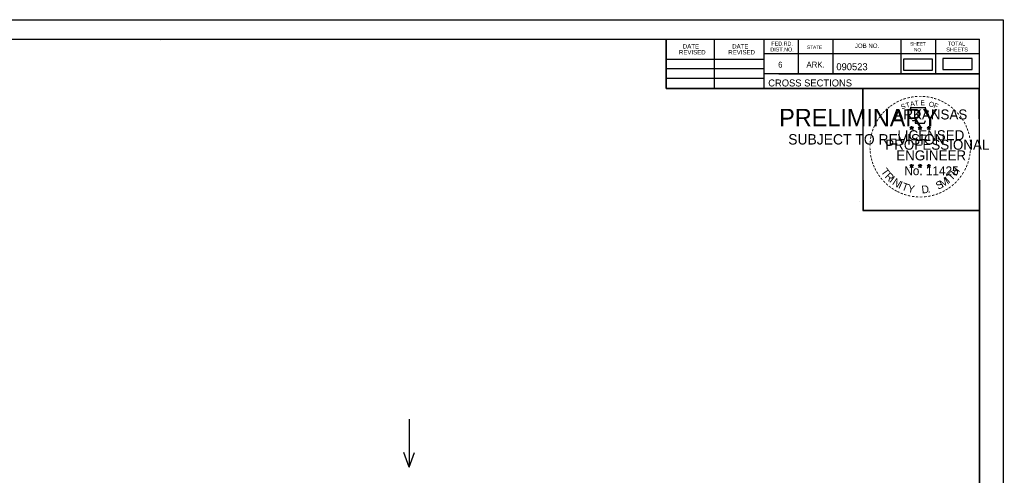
# Model space of a CAD drawing. Extents: x 1406028 to 1412453, y 321733 to 325986.
# Drawn here: x 1406556.2 to 1406752.8, y 323761.7 to 323852.7 of the extents above; entities that cross this region are included whole.
import ezdxf

# ---------------------------------------------------------------- set-up
doc = ezdxf.new("R2010")
doc.units = 0
for name, color, linetype in [('R_Border', 7, 'Continuous'), ('R_Border PE', 7, 'Continuous'), ('R_Border Prem', 7, 'Continuous'), ('R_Fin Surface', 7, 'Continuous'), ('R_No Plot', 7, 'Continuous'), ('R_Water Annot', 7, 'Continuous')]:
    doc.layers.add(name, color=color, linetype=linetype)

msp = doc.modelspace()

# ---------------------------------------------------------------- linework, layer by layer
at = {"layer": 'R_Border'}
for p, q in [((1406431.89, 323848.82), (1406748.07, 323848.82)), ((1406584.41, 323848.56), (1406584.41, 323848.56)), ((1406584.41, 323848.56), (1406584.41, 323848.56)), ((1406685.43, 323838.94), (1406685.43, 323848.82)), ((1406695.11, 323838.94), (1406695.11, 323848.82)), ((1406704.97, 323848.82), (1406704.97, 323838.94)), ((1406711.81, 323848.82), (1406711.81, 323841.88)), ((1406718.75, 323848.82), (1406718.75, 323841.88)), ((1406732.33, 323848.82), (1406732.33, 323841.88)), ((1406739.27, 323848.82), (1406739.27, 323841.88)), ((1406748.07, 323643.36), (1406748.07, 323848.82)), ((1406685.43, 323844.8), (1406704.97, 323844.8)), ((1406748.07, 323845.88), (1406704.97, 323845.88)), ((1406748.07, 323845.9), (1406748.07, 323845.9)), ((1406685.43, 323842.94), (1406704.97, 323842.94)), ((1406685.43, 323841), (1406704.97, 323841)), ((1406748.07, 323841.88), (1406704.97, 323841.88)), ((1406707.93, 323841.88), (1406748.07, 323841.88)), ((1406748.07, 323838.94), (1406685.43, 323838.94))]:
    msp.add_line(p, q, dxfattribs=at)
at = {"layer": 'R_Border PE'}
for p, q in [((1406734.15, 323831.19), (1406734.5, 323831.08)), ((1406734.15, 323831.19), (1406734.41, 323831.15)), ((1406734.15, 323831.19), (1406734.39, 323831.07)), ((1406734.29, 323830.78), (1406734.5, 323831.08)), ((1406734.29, 323830.78), (1406734.41, 323831.03)), ((1406734.29, 323830.78), (1406734.5, 323831)), ((1406734.5, 323831.44), (1406734.46, 323831.19)), ((1406734.5, 323831.08), (1406734.5, 323831.44)), ((1406734.5, 323831.44), (1406734.55, 323831.19)), ((1406734.85, 323831.19), (1406734.5, 323831.08)), ((1406734.72, 323830.78), (1406734.5, 323831.08)), ((1406734.72, 323830.78), (1406734.5, 323831)), ((1406734.85, 323831.19), (1406734.56, 323831.14)), ((1406734.72, 323830.78), (1406734.58, 323831.07)), ((1406734.85, 323831.19), (1406734.65, 323831.09)), ((1406735.82, 323831.19), (1406736.17, 323831.08)), ((1406735.82, 323831.19), (1406736.08, 323831.15)), ((1406735.82, 323831.19), (1406736.06, 323831.07)), ((1406735.96, 323830.78), (1406736.17, 323831.08)), ((1406735.96, 323830.78), (1406736.08, 323831.03)), ((1406735.96, 323830.78), (1406736.17, 323831)), ((1406736.17, 323831.44), (1406736.13, 323831.19)), ((1406736.17, 323831.08), (1406736.17, 323831.44)), ((1406736.17, 323831.44), (1406736.22, 323831.19)), ((1406736.52, 323831.19), (1406736.17, 323831.08)), ((1406736.39, 323830.78), (1406736.17, 323831.08)), ((1406736.39, 323830.78), (1406736.17, 323831)), ((1406736.52, 323831.19), (1406736.23, 323831.14)), ((1406736.39, 323830.78), (1406736.25, 323831.07)), ((1406736.52, 323831.19), (1406736.32, 323831.09)), ((1406737.59, 323831.18), (1406737.94, 323831.07)), ((1406737.59, 323831.18), (1406737.84, 323831.13)), ((1406737.59, 323831.18), (1406737.83, 323831.06)), ((1406737.72, 323830.77), (1406737.94, 323831.07)), ((1406737.72, 323830.77), (1406737.85, 323831.01)), ((1406737.72, 323830.77), (1406737.94, 323830.99)), ((1406737.94, 323831.43), (1406737.9, 323831.18)), ((1406737.94, 323831.07), (1406737.94, 323831.43)), ((1406737.94, 323831.43), (1406737.99, 323831.18)), ((1406738.28, 323831.18), (1406737.94, 323831.07)), ((1406738.15, 323830.77), (1406737.94, 323831.07)), ((1406738.15, 323830.77), (1406737.94, 323830.98)), ((1406738.28, 323831.18), (1406738, 323831.13)), ((1406738.15, 323830.77), (1406738.01, 323831.06)), ((1406738.28, 323831.18), (1406738.08, 323831.08)), ((1406734.15, 323823.62), (1406734.5, 323823.51)), ((1406734.15, 323823.62), (1406734.4, 323823.57)), ((1406734.15, 323823.62), (1406734.39, 323823.5)), ((1406734.28, 323823.21), (1406734.5, 323823.51)), ((1406734.28, 323823.21), (1406734.41, 323823.45)), ((1406734.28, 323823.21), (1406734.5, 323823.43)), ((1406734.5, 323823.87), (1406734.46, 323823.62)), ((1406734.5, 323823.51), (1406734.5, 323823.87)), ((1406734.5, 323823.87), (1406734.55, 323823.62)), ((1406734.85, 323823.62), (1406734.5, 323823.51)), ((1406734.71, 323823.21), (1406734.5, 323823.51)), ((1406734.71, 323823.21), (1406734.5, 323823.42)), ((1406734.85, 323823.62), (1406734.56, 323823.57)), ((1406734.71, 323823.21), (1406734.58, 323823.5)), ((1406734.85, 323823.62), (1406734.64, 323823.52)), ((1406735.82, 323823.62), (1406736.17, 323823.51)), ((1406735.82, 323823.62), (1406736.07, 323823.57)), ((1406735.82, 323823.62), (1406736.06, 323823.5)), ((1406735.95, 323823.21), (1406736.17, 323823.51)), ((1406735.95, 323823.21), (1406736.08, 323823.45)), ((1406735.95, 323823.21), (1406736.17, 323823.43)), ((1406736.17, 323823.87), (1406736.13, 323823.62)), ((1406736.17, 323823.51), (1406736.17, 323823.87)), ((1406736.17, 323823.87), (1406736.22, 323823.62)), ((1406736.52, 323823.62), (1406736.17, 323823.51)), ((1406736.38, 323823.21), (1406736.17, 323823.51)), ((1406736.38, 323823.21), (1406736.17, 323823.42)), ((1406736.52, 323823.62), (1406736.23, 323823.57)), ((1406736.38, 323823.21), (1406736.24, 323823.5)), ((1406736.52, 323823.62), (1406736.31, 323823.52)), ((1406737.59, 323823.61), (1406737.94, 323823.5)), ((1406737.59, 323823.61), (1406737.84, 323823.56)), ((1406737.59, 323823.61), (1406737.82, 323823.49)), ((1406737.72, 323823.2), (1406737.94, 323823.5)), ((1406737.72, 323823.2), (1406737.85, 323823.44)), ((1406737.72, 323823.2), (1406737.93, 323823.42)), ((1406737.94, 323823.86), (1406737.89, 323823.61)), ((1406738.15, 323823.2), (1406737.93, 323823.41)), ((1406737.94, 323823.5), (1406737.94, 323823.86)), ((1406737.94, 323823.86), (1406737.98, 323823.61)), ((1406738.28, 323823.61), (1406737.94, 323823.5)), ((1406738.15, 323823.2), (1406737.94, 323823.5)), ((1406738.28, 323823.61), (1406738, 323823.56)), ((1406738.15, 323823.2), (1406738.01, 323823.49)), ((1406738.28, 323823.61), (1406738.08, 323823.51))]:
    msp.add_line(p, q, dxfattribs=at)
for points in [[(1406734.2, 323835.07), (1406734.46, 323834.24)], [(1406737.71, 323834.15), (1406737.85, 323834.43), (1406737.16, 323834.41), (1406737.31, 323835.07), (1406734.2, 323835.07)], [(1406734.69, 323832.65), (1406734.69, 323832.56), (1406735.25, 323832.54), (1406735.2, 323832.07), (1406737.07, 323832.07), (1406737.27, 323832.6)], [(1406734.5, 323831.44), (1406734.72, 323830.78), (1406734.15, 323831.19), (1406734.85, 323831.19), (1406734.29, 323830.78), (1406734.5, 323831.44)], [(1406736.17, 323831.44), (1406736.39, 323830.78), (1406735.82, 323831.19), (1406736.52, 323831.19), (1406735.96, 323830.78), (1406736.17, 323831.44)], [(1406737.94, 323831.43), (1406738.15, 323830.77), (1406737.59, 323831.18), (1406738.28, 323831.18), (1406737.72, 323830.77), (1406737.94, 323831.43)], [(1406734.5, 323823.87), (1406734.71, 323823.21), (1406734.15, 323823.62), (1406734.85, 323823.62), (1406734.28, 323823.21), (1406734.5, 323823.87)], [(1406736.17, 323823.87), (1406736.38, 323823.21), (1406735.82, 323823.62), (1406736.52, 323823.62), (1406735.95, 323823.21), (1406736.17, 323823.87)], [(1406737.94, 323823.86), (1406738.15, 323823.2), (1406737.59, 323823.61), (1406738.28, 323823.61), (1406737.72, 323823.2), (1406737.94, 323823.86)]]:
    msp.add_lwpolyline(points, dxfattribs=at)
for centre, radius in [((1406734.5, 323831.08), 0.172), ((1406734.5, 323831.08), 0.145), ((1406734.5, 323831.08), 0.116), ((1406734.5, 323831.08), 0.0991), ((1406734.5, 323831.08), 0.0747), ((1406734.5, 323831.08), 0.0495), ((1406734.5, 323831.08), 0.0296), ((1406736.17, 323831.08), 0.172), ((1406736.17, 323831.08), 0.145), ((1406736.17, 323831.08), 0.116), ((1406736.17, 323831.08), 0.0991), ((1406736.17, 323831.08), 0.0747), ((1406736.17, 323831.08), 0.0495), ((1406736.17, 323831.08), 0.0296), ((1406737.94, 323831.07), 0.172), ((1406737.94, 323831.07), 0.145), ((1406737.94, 323831.07), 0.116), ((1406737.94, 323831.07), 0.0991), ((1406737.94, 323831.07), 0.0747), ((1406737.94, 323831.07), 0.0495), ((1406737.94, 323831.07), 0.0296), ((1406734.5, 323823.51), 0.172), ((1406734.5, 323823.51), 0.145), ((1406734.5, 323823.51), 0.116), ((1406734.5, 323823.51), 0.0991), ((1406734.5, 323823.51), 0.0747), ((1406734.5, 323823.51), 0.0495), ((1406734.5, 323823.51), 0.0296), ((1406736.17, 323823.51), 0.172), ((1406736.17, 323823.51), 0.145), ((1406736.17, 323823.51), 0.116), ((1406736.17, 323823.51), 0.0991), ((1406736.17, 323823.51), 0.0747), ((1406736.17, 323823.51), 0.0495), ((1406736.17, 323823.51), 0.0296), ((1406737.93, 323823.5), 0.172), ((1406737.93, 323823.5), 0.145), ((1406737.93, 323823.5), 0.116), ((1406737.93, 323823.5), 0.0991), ((1406737.93, 323823.5), 0.0747), ((1406737.93, 323823.5), 0.0495), ((1406737.93, 323823.5), 0.0296)]:
    msp.add_circle(centre, radius, dxfattribs=at)
at = {"layer": 'R_Fin Surface'}
for points in [[(1406732.85, 323842.65), (1406738.68, 323842.65), (1406738.68, 323844.84), (1406732.85, 323844.84)], [(1406740.76, 323842.76), (1406746.59, 323842.76), (1406746.59, 323844.95), (1406740.76, 323844.95)]]:
    msp.add_lwpolyline(points, close=True, dxfattribs=at)
at = {"layer": 'R_No Plot'}
for p, q in [((1406419.49, 323852.71), (1406752.82, 323852.71)), ((1406724.1, 323816.48), (1406724.1, 323816.48))]:
    msp.add_line(p, q, dxfattribs=at)
for points in [[(1406419.48, 323852.71), (1406752.82, 323852.71), (1406752.82, 323639.37), (1406419.48, 323639.37)], [(1406665.81, 323848.82), (1406685.43, 323848.82), (1406685.43, 323838.94), (1406701.54, 323838.94), (1406724.74, 323838.94), (1406724.74, 323814.6), (1406748.07, 323814.6), (1406748.07, 323643.36), (1406431.89, 323643.36), (1406431.89, 323848.82)], [(1406724.74, 323838.94), (1406747.95, 323838.94), (1406748.07, 323814.6), (1406724.86, 323814.6)]]:
    msp.add_lwpolyline(points, close=True, dxfattribs=at)
at = {"layer": 'R_Water Annot'}
for p, q in [((1406634.04, 323772.88), (1406634.04, 323763.31)), ((1406634.04, 323763.31), (1406632.97, 323766.24)), ((1406634.04, 323763.31), (1406635.1, 323766.24))]:
    msp.add_line(p, q, dxfattribs=at)

# ---------------------------------------------------------------- texts
at = {"layer": 'R_Border'}
for s, height, p in [('FED.RD.', 0.782, (1406706.45, 323847.54)), ('JOB NO.', 0.879, (1406723.15, 323847.06)), ('SHEET', 0.684, (1406734.19, 323847.54)), ('TOTAL', 0.782, (1406741.71, 323847.54)), ('REVISED', 0.879, (1406687.99, 323845.77)), ('DATE', 0.879, (1406688.77, 323846.95)), ('REVISED', 0.879, (1406697.85, 323845.77)), ('DATE', 0.879, (1406698.63, 323846.95)), ('DIST.NO.', 0.782, (1406706.25, 323846.36)), ('STATE', 0.684, (1406713.57, 323846.86)), ('NO.', 0.684, (1406734.97, 323846.36)), ('SHEETS', 0.782, (1406741.43, 323846.36)), ('6', 1.17, (1406707.81, 323843.14)), ('ARK.', 1.172, (1406713.47, 323843.14)), ('090523', 1.4, (1406719.45, 323842.61)), ('CROSS SECTIONS', 1.4, (1406705.83, 323839.37))]:
    msp.add_text(s, height=height, rotation=360, dxfattribs=at).set_placement(p)
at = {"layer": 'R_Border PE'}
for s, height, rotation, p in [('-', 1.6, 34.0636, (1406731.08, 323835.24)), ('-', 1.6, 28.7918, (1406731.68, 323835.61)), ('-', 1.6, 24.3072, (1406732.31, 323835.93)), ('-', 1.6, 19.1761, (1406732.94, 323836.2)), ('T', 1, 16.4036, (1406733.46, 323835.08)), ('-', 1.6, 13.6301, (1406733.69, 323836.44)), ('A', 1, 11.2132, (1406734.29, 323835.33)), ('-', 1.6, 10.2193, (1406734.37, 323836.6)), ('T', 1, 6.0228, (1406735.14, 323835.49)), ('-', 1.6, 5.8968, (1406735.1, 323836.71)), ('-', 1.6, 0.1862, (1406735.87, 323836.78)), ('E', 1, 0.8323, (1406736.24, 323835.6)), ('-', 1.6, 357.743, (1406736.6, 323836.77)), ('-', 1.6, 352.1617, (1406737.34, 323836.71)), ('O', 1, 350.4515, (1406737.85, 323835.39)), ('-', 1.6, 347.2049, (1406738.06, 323836.6)), ('-', 1.6, 342.3362, (1406738.69, 323836.44)), ('-', 1.6, 337.8551, (1406739.43, 323836.22)), ('-', 1.6, 334.1211, (1406740.06, 323835.95)), ('-', 1.6, 329.6409, (1406740.64, 323835.67)), ('-', 1.6, 48.423, (1406729.14, 323833.57)), ('-', 1.6, 42.9622, (1406729.59, 323834.05)), ('-', 1.6, 38.9507, (1406730.03, 323834.47)), ('-', 1.6, 36.2317, (1406730.5, 323834.84)), ('ARKANSAS', 2, 360, (1406731.05, 323832.78)), ('S', 1, 21.594, (1406732.55, 323834.75)), ('F', 1, 340.0707, (1406738.8, 323835.17)), ('-', 1.6, 325.8627, (1406741.28, 323835.3)), ('-', 1.6, 320.5297, (1406741.89, 323834.88)), ('-', 1.6, 315.5786, (1406742.49, 323834.39)), ('-', 1.6, 309.8797, (1406743.06, 323833.84)), ('-', 1.6, 62.8713, (1406727.69, 323831.38)), ('-', 1.6, 58.0706, (1406728, 323831.99)), ('-', 1.6, 54.2325, (1406728.33, 323832.52)), ('-', 1.6, 50.6142, (1406728.74, 323833.09)), ('-', 1.6, 306.6522, (1406743.58, 323833.24)), ('-', 1.4, 303.6753, (1406744.07, 323832.67)), ('-', 1.6, 299.6684, (1406744.39, 323832.06)), ('-', 1.6, 72.3945, (1406727.21, 323830.14)), ('-', 1.6, 67.7743, (1406727.43, 323830.77)), ('LICENSED', 2, 360, (1406731.65, 323828.63)), ('DWB', 0.01, 360, (1406734.49, 323831.07)), ('DWB', 0.01, 360, (1406736.16, 323831.07)), ('DWB', 0.01, 360, (1406737.92, 323831.06)), ('-', 1.6, 294.6628, (1406744.71, 323831.45)), ('-', 1.6, 290.5728, (1406744.97, 323830.87)), ('-', 1.6, 285.1233, (1406745.2, 323830.29)), ('-', 1.6, 85.1863, (1406726.81, 323828.02)), ('-', 1.6, 81.2013, (1406726.88, 323828.71)), ('-', 1.6, 75.461, (1406727.02, 323829.42)), ('PROFESSIONAL', 2, 360, (1406729.22, 323826.73)), ('-', 1.6, 280.5493, (1406745.4, 323829.55)), ('-', 1.6, 276.5962, (1406745.57, 323828.78)), ('-', 1.6, 94.1959, (1406726.82, 323826.59)), ('-', 1.6, 89.0622, (1406726.78, 323827.32)), ('-', 1.6, 98.9479, (1406726.89, 323825.93)), ('ENGINEER', 2, 360, (1406731.41, 323824.6)), ('-', 1.6, 263.5172, (1406745.64, 323826.76)), ('-', 1.6, 274.3301, (1406745.63, 323828.06)), ('-', 1.6, 269.9407, (1406745.66, 323827.43)), ('-', 1.6, 101.7149, (1406727.02, 323825.19)), ('-', 1.6, 105.4578, (1406727.19, 323824.6)), ('-', 1.6, 109.0874, (1406727.4, 323823.97)), ('-', 1.6, 252.8681, (1406745.28, 323824.71)), ('-', 1.6, 255.7626, (1406745.46, 323825.43)), ('-', 1.6, 260.9953, (1406745.57, 323826.11)), ('-', 1.6, 114.0643, (1406727.66, 323823.37)), ('-', 1.6, 115.7289, (1406727.96, 323822.75)), ('-', 1.6, 120.4471, (1406728.32, 323822.17)), ('T', 1.54, 306.0406, (1406728.26, 323822.34)), ('No. 11425', 1.757, 360, (1406733.04, 323821.65)), ('DWB', 0.01, 360, (1406734.49, 323823.5)), ('DWB', 0.01, 360, (1406736.16, 323823.5)), ('DWB', 0.01, 360, (1406737.92, 323823.49)), ('H', 1.54, 54.6088, (1406743.38, 323821.38)), ('-', 1.6, 244.6197, (1406744.79, 323823.41)), ('-', 1.6, 247.8887, (1406745.06, 323824.04)), ('-', 1.6, 125.8934, (1406728.72, 323821.61)), ('-', 1.6, 130.7181, (1406729.18, 323821.05)), ('-', 1.6, 134.2238, (1406729.7, 323820.51)), ('R', 1.54, 314.005, (1406729.02, 323821.3)), ('I', 1.54, 321.9694, (1406729.92, 323820.36)), ('N', 1.54, 326.5002, (1406730.49, 323819.89)), ('I', 1.54, 335.3603, (1406731.7, 323819.11)), ('S', 1.54, 26.9312, (1406739.8, 323818.71)), ('M', 1.54, 32.6563, (1406740.64, 323819.11)), ('I', 1.54, 42.1136, (1406741.93, 323819.96)), ('T', 1.54, 46.6444, (1406742.49, 323820.44)), ('-', 1.6, 225.7653, (1406743.09, 323820.88)), ('-', 1.6, 231.2538, (1406743.57, 323821.44)), ('-', 1.6, 233.8452, (1406744, 323822.01)), ('-', 1.6, 239.0712, (1406744.4, 323822.66)), ('-', 1.6, 138.9338, (1406730.22, 323820.04)), ('-', 1.6, 144.6463, (1406730.78, 323819.64)), ('-', 1.6, 148.0898, (1406731.34, 323819.27)), ('-', 1.6, 151.5704, (1406731.92, 323818.94)), ('-', 1.6, 154.6002, (1406732.44, 323818.7)), ('T', 1.54, 339.8912, (1406732.36, 323818.78)), ('Y', 1.54, 347.8556, (1406733.58, 323818.33)), ('D', 1.54, 6.3969, (1406736.56, 323817.98)), ('-', 1.6, 207.3568, (1406740.93, 323819.16)), ('-', 1.6, 212.2491, (1406741.48, 323819.51)), ('-', 1.6, 215.7363, (1406742.02, 323819.89)), ('-', 1.6, 221.0851, (1406742.57, 323820.37)), ('-', 1.6, 158.5612, (1406733.07, 323818.44)), ('-', 1.6, 162.7983, (1406733.75, 323818.23)), ('-', 1.6, 167.5555, (1406734.47, 323818.06)), ('-', 1.6, 173.1155, (1406735.24, 323817.95)), ('-', 1.6, 176.5183, (1406735.99, 323817.9)), ('-', 1.6, 181.5918, (1406736.73, 323817.92)), ('-', 1.6, 185.8167, (1406737.54, 323818)), ('-', 1.6, 191.2858, (1406738.28, 323818.13)), ('.', 1.54, 13.7642, (1406737.75, 323818.1)), ('-', 1.6, 195.4743, (1406739.01, 323818.33)), ('-', 1.6, 200.7184, (1406739.68, 323818.57)), ('-', 1.6, 204.2516, (1406740.3, 323818.84))]:
    msp.add_text(s, height=height, rotation=rotation, dxfattribs=at).set_placement(p)
at = {"layer": 'R_Border Prem'}
for s, height, p in [('PRELIMINARY', 3.5, (1406708.02, 323831.4)), ('DWB', 0.01, (1406708.77, 323833.25)), ('SUBJECT TO REVISION', 2.0751, (1406709.83, 323827.77))]:
    msp.add_text(s, height=height, rotation=360, dxfattribs=at).set_placement(p)

doc.saveas('drawing.dxf')
